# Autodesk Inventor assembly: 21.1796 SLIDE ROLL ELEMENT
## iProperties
Created: 2007-05
Part Number: 21.1796 SLIDE ROLL ELEMENT
Document SubType Name: Assembly
Designer: Andy Moles
Mass: 99.4955 g
Surface Area: 179.715 cm^2
Volume: 33.0271 cm^3
Density: 3.01254 g/cm^3
Author: Andy Moles
